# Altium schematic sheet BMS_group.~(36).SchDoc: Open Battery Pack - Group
size A3; Author: Morgane Vallée; Revision: 1.0; SheetNumber: 2; SheetTotal: 3
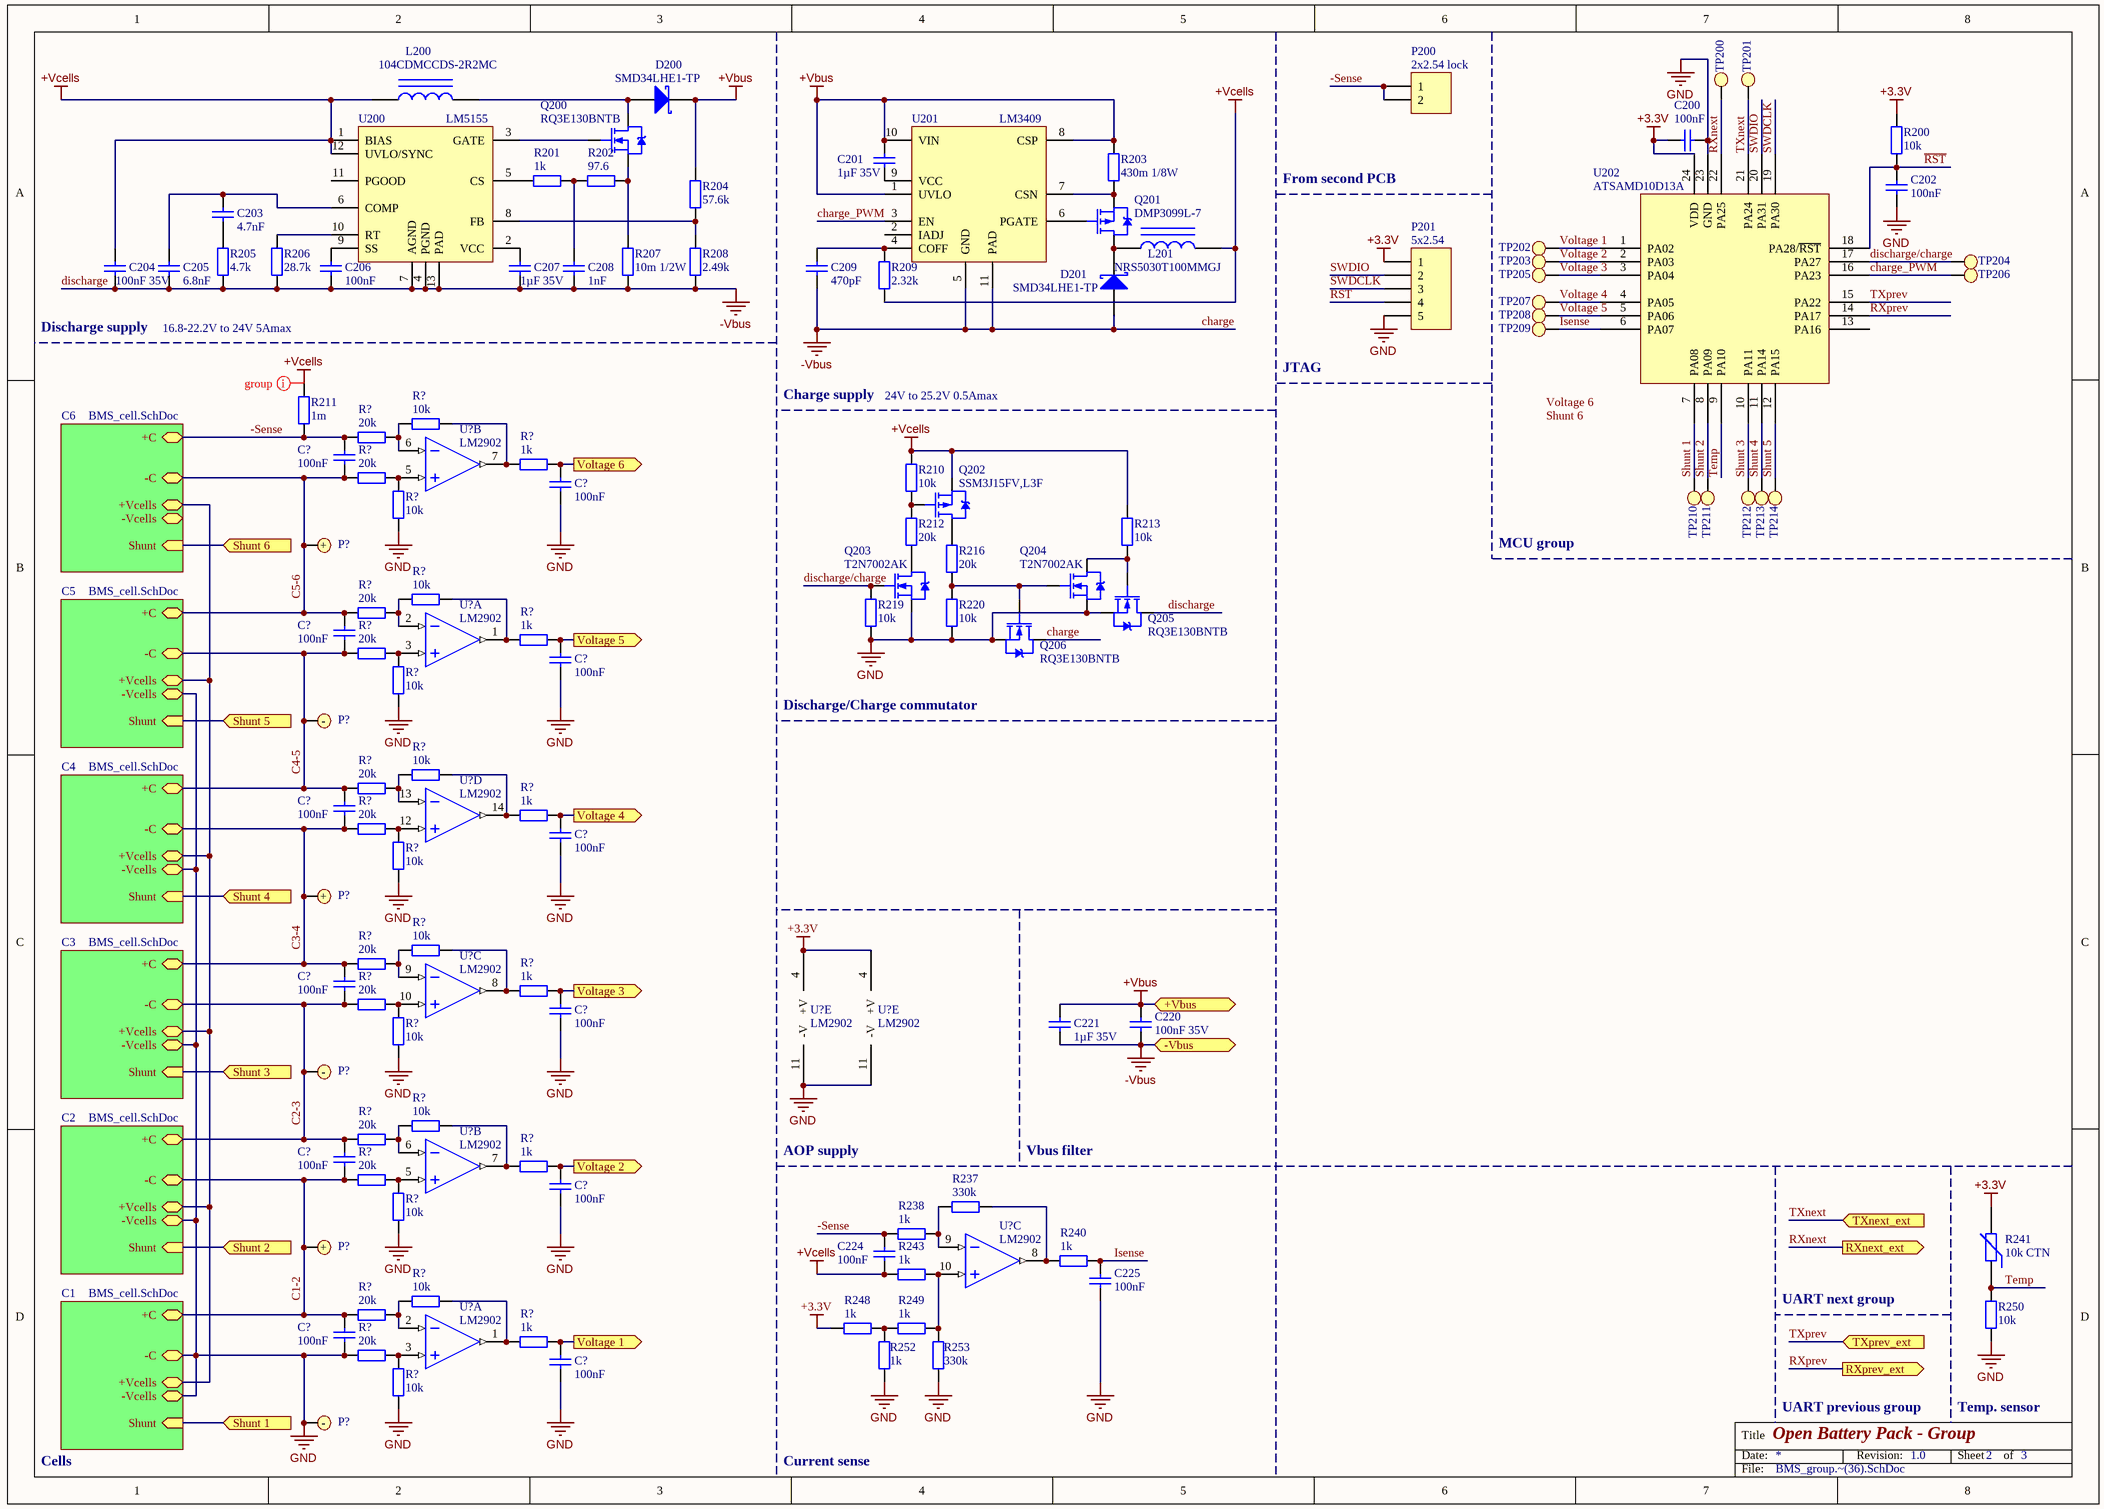
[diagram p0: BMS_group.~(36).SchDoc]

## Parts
(Parts that share a designator on the sheet are numbered #1, #2 ... from top to bottom, then left to right.)
C200  100nF  [C0603]
C201  1µF 35V  [C0805]
C202  100nF  [C0603]
C203  4.7nF  [C0603]
C204  100nF 35V  [C0603]
C205  6.8nF  [C0603]
C206  100nF  [C0603]
C207  1µF 35V  [C0805]
C208  1nF  [C0603]
C209  470pF  [C0603]
C220  100nF 35V  [C0603]
C221  1µF 35V  [C0805]
C224  100nF  [C0603]
C225  100nF  [C0603]
C?#1  100nF  [C0603]
C?#2  100nF  [C0603]
C?#3  100nF  [C0603]
C?#4  100nF  [C0603]
C?#5  100nF  [C0603]
C?#6  100nF  [C0603]
C?#7  100nF  [C0603]
C?#8  100nF  [C0603]
C?#9  100nF  [C0603]
C?#10  100nF  [C0603]
C?#11  100nF  [C0603]
C?#12  100nF  [C0603]
D200  SMD34LHE1-TP  [SOD-123H]
D201  SMD34LHE1-TP  [SOD-123H]
L200  104CDMCCDS-2R2MC  [SELF_SMD_8x8]
L201  NRS5030T100MMGJ  [SELF_SMD_4.9x4.9]
P200  2x2.54 lock  [MOLEX KK 0022272021]
P201  5x2.54  [HDR1X5]
P?#1  Bat+  [Keystone 241]  (value not drawn)
P?#2  Bat-  [Keystone 2993]  (value not drawn)
P?#3  Bat+  [Keystone 241]  (value not drawn)
P?#4  Bat-  [Keystone 2993]  (value not drawn)
P?#5  Bat+  [Keystone 241]  (value not drawn)
P?#6  Bat-  [Keystone 2993]  (value not drawn)
Q200  RQ3E130BNTB  [INFINEON PG-TSDSON-8]
Q201  DMP3099L-7  [DIODES SOT-23-3]
Q202  SSM3J15FV,L3F  [DIODES SOT-23-3]
Q203  T2N7002AK  [DIODES SOT-23-3]
Q204  T2N7002AK  [DIODES SOT-23-3]
Q205  RQ3E130BNTB  [INFINEON PG-TSDSON-8]
Q206  RQ3E130BNTB  [INFINEON PG-TSDSON-8]
R200  10k  [R0603]
R201  1k  [R0603]
R202  97.6  [R0603]
R203  430m 1/8W  [R0603]
R204  57.6k  [R0603]
R205  4.7k  [R0603]
R206  28.7k  [R0603]
R207  10m 1/2W  [R1206]
R208  2.49k  [R0603]
R209  2.32k  [R0603]
R210  10k  [R0603]
R211  1m  [R1206]
R212  20k  [R0603]
R213  10k  [R0603]
R216  20k  [R0603]
R219  10k  [R0603]
R220  10k  [R0603]
R237  330k  [R0603]
R238  1k  [R0603]
R240  1k  [R0603]
R241  10k CTN  [NTC 0402/1005]
R243  1k  [R0603]
R248  1k  [R0603]
R249  1k  [R0603]
R250  10k  [R0603]
R252  1k  [R0603]
R253  330k  [R0603]
R?#1  10k  [R0603]
R?#2  20k  [R0603]
R?#3  1k  [R0603]
R?#4  20k  [R0603]
R?#5  10k  [R0603]
R?#6  10k  [R0603]
R?#7  20k  [R0603]
R?#8  1k  [R0603]
R?#9  20k  [R0603]
R?#10  10k  [R0603]
R?#11  10k  [R0603]
R?#12  20k  [R0603]
R?#13  1k  [R0603]
R?#14  20k  [R0603]
R?#15  10k  [R0603]
R?#16  10k  [R0603]
R?#17  20k  [R0603]
R?#18  1k  [R0603]
R?#19  20k  [R0603]
R?#20  10k  [R0603]
R?#21  10k  [R0603]
R?#22  20k  [R0603]
R?#23  1k  [R0603]
R?#24  20k  [R0603]
R?#25  10k  [R0603]
R?#26  10k  [R0603]
R?#27  20k  [R0603]
R?#28  1k  [R0603]
R?#29  20k  [R0603]
R?#30  10k  [R0603]
TP200  Test Point  [Test Point]  (value not drawn)
TP201  Test Point  [Test Point]  (value not drawn)
TP202  Test Point  [Test Point]  (value not drawn)
TP203  Test Point  [Test Point]  (value not drawn)
TP204  Test Point  [Test Point]  (value not drawn)
TP205  Test Point  [Test Point]  (value not drawn)
TP206  Test Point  [Test Point]  (value not drawn)
TP207  Test Point  [Test Point]  (value not drawn)
TP208  Test Point  [Test Point]  (value not drawn)
TP209  Test Point  [Test Point]  (value not drawn)
TP210  Test Point  [Test Point]  (value not drawn)
TP211  Test Point  [Test Point]  (value not drawn)
TP212  Test Point  [Test Point]  (value not drawn)
TP213  Test Point  [Test Point]  (value not drawn)
TP214  Test Point  [Test Point]  (value not drawn)
U200  LM5155  [TI WSON-12]
U201  LM3409  [TI MSOP-10 DGQ]
U202  ATSAMD10D13A  [SMSC QFN-24 4x4MM]
U?#1  LM2902  [Atmel SO-14 14S1]  (part B of 5)
U?#2  LM2902  [Atmel SO-14 14S1]  (part A of 5)
U?#3  LM2902  [Atmel SO-14 14S1]  (part D of 5)
U?#4  LM2902  [Atmel SO-14 14S1]  (part C of 5)
U?#5  LM2902  [Atmel SO-14 14S1]  (part E of 5)
U?#6  LM2902  [Atmel SO-14 14S1]  (part E of 5)
U?#7  LM2902  [Atmel SO-14 14S1]  (part B of 5)
U?#8  LM2902  [Atmel SO-14 14S1]  (part C of 5)
U?#9  LM2902  [Atmel SO-14 14S1]  (part A of 5)

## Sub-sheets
C1 = BMS_cell.SchDoc: -C, +C, +Vcells, -Vcells, Shunt (in)
C2 = BMS_cell.SchDoc: -C, +C, +Vcells, -Vcells, Shunt (in)
C3 = BMS_cell.SchDoc: -C, +C, +Vcells, -Vcells, Shunt (in)
C4 = BMS_cell.SchDoc: -C, +C, +Vcells, -Vcells, Shunt (in)
C5 = BMS_cell.SchDoc: -C, +C, +Vcells, -Vcells, Shunt (in)
C6 = BMS_cell.SchDoc: -C, +C, +Vcells, -Vcells, Shunt (in)

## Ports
+Vbus, -Vbus, RXnext_ext (out), RXprev_ext (out), Shunt 1 (in), Shunt 2 (in), Shunt 3 (in), Shunt 4 (in), Shunt 5 (in), Shunt 6 (in), TXnext_ext (in), TXprev_ext (in), Voltage 1 (out), Voltage 2 (out), Voltage 3 (out), Voltage 4 (out), Voltage 5 (out), Voltage 6 (out)

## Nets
+3.3V: C200.2 P201.1 R200.2 R241.2 R248.2 U202.24(VDD) U?#5.4(+V) U?#6.4(+V)
+Vbus: C201.1 C220.1 C221.1 D200.3(K) R203.2 R204.2 U201.1(UVLO) U201.8(CSP) U201.10(VIN) ; port +Vbus
+Vcells: C204.1 C224.2 L200.1 L201.2 Q202.2(S) R209.2 R210.2 R211.2 R213.2 R243.2 U200.1(BIAS) U200.12(UVLO/SYNC)
charge: C204.2 C205.2 C206.2 C207.2 C208.2 C209.2 C220.2 C221.2 D201.1(A) Q205.3(D) Q206.3(D) R205.1 R206.1 R207.1 R208.1 U200.4(PGND) U200.7(AGND) U200.13(PAD) U201.5(GND) U201.11(PAD) ; port -Vbus  [also labelled -Vbus, discharge]
GND: C200.1 C202.1 C225.2 C?#2.2 C?#4.2 C?#6.2 C?#8.2 C?#10.2 C?#11.2 C?#12.2 P201.5 P?#6.1 Q203.2(S) Q204.2(S) Q205.2(S) Q206.2(S) R219.1 R220.1 R250.2 R252.2 R253.1 R?#5.2 R?#10.2 R?#15.2 R?#20.2 R?#25.2 R?#29.2 R?#30.2 U202.23(GND) U?#5.11(-V) U?#6.11(-V) ; sheet C1/-C, sheet C1/-Vcells, sheet C2/-Vcells, sheet C3/-Vcells, sheet C4/-Vcells, sheet C5/-Vcells
-Sense: C224.1 C?#1.1 P200.1 P200.2 R211.1 R238.1 R?#2.1 ; sheet C6/+C
C1-2: C?#9.2 C?#11.1 P?#5.1 R?#24.2 R?#27.1 ; sheet C1/+C, sheet C2/-C
C2-3: C?#7.2 C?#9.1 P?#4.1 R?#19.2 R?#22.1 ; sheet C2/+C, sheet C3/-C
C3-4: C?#5.2 C?#7.1 P?#3.1 R?#14.2 R?#17.1 ; sheet C3/+C, sheet C4/-C
C4-5: C?#3.2 C?#5.1 P?#2.1 R?#9.2 R?#12.1 ; sheet C4/+C, sheet C5/-C
C5-6: C?#1.2 C?#3.1 P?#1.1 R?#4.2 R?#7.1 ; sheet C5/+C, sheet C6/-C
charge_PWM: TP206.1 U201.3(EN) U202.16(PA23)
discharge/charge: Q203.1(G) R219.2 TP204.1 U202.17(PA27)
Isense: C225.1 R240.1 TP209.1 U202.6(PA07)
~{RST}: C202.2 P201.4 R200.1 U202.18(PA28/~{RST})
RXnext: TP200.1 U202.22(PA25) ; port RXnext_ext
RXprev: U202.14(PA17) ; port RXprev_ext
Shunt 1: TP210.1 U202.7(PA08)
Shunt 1: port Shunt 1, sheet C1/Shunt  [a separate net that carries the same name]
Shunt 2: TP211.1 U202.8(PA09)
Shunt 2: port Shunt 2, sheet C2/Shunt  [a separate net that carries the same name]
Shunt 3: TP212.1 U202.10(PA11)
Shunt 3: port Shunt 3, sheet C3/Shunt  [a separate net that carries the same name]
Shunt 4: TP213.1 U202.11(PA14)
Shunt 4: port Shunt 4, sheet C4/Shunt  [a separate net that carries the same name]
Shunt 5: TP214.1 U202.12(PA15)
Shunt 5: port Shunt 5, sheet C5/Shunt  [a separate net that carries the same name]
Shunt 6: port Shunt 6, sheet C6/Shunt
SWDCLK: P201.3 U202.19(PA30)
SWDIO: P201.2 U202.20(PA31)
Temp: R241.1 R250.1 U202.9(PA10)
TXnext: TP201.1 U202.21(PA24) ; port TXnext_ext
TXprev: U202.15(PA22) ; port TXprev_ext
Voltage 1: TP202.1 U202.1(PA02)
Voltage 1: C?#12.1 R?#28.1 ; port Voltage 1  [a separate net that carries the same name]
Voltage 2: TP203.1 U202.2(PA03)
Voltage 2: C?#10.1 R?#23.1 ; port Voltage 2  [a separate net that carries the same name]
Voltage 3: TP205.1 U202.3(PA04)
Voltage 3: C?#8.1 R?#18.1 ; port Voltage 3  [a separate net that carries the same name]
Voltage 4: TP207.1 U202.4(PA05)
Voltage 4: C?#6.1 R?#13.1 ; port Voltage 4  [a separate net that carries the same name]
Voltage 5: TP208.1 U202.5(PA06)
Voltage 5: C?#4.1 R?#8.1 ; port Voltage 5  [a separate net that carries the same name]
Voltage 6: C?#2.1 R?#3.1 ; port Voltage 6
NetC201_2: C201.2 U201.9(VCC)
NetC203_1: C203.1 C205.1 U200.6(COMP)
NetC203_2: C203.2 R205.2
NetC206_1: C206.1 U200.9(SS)
NetC207_1: C207.1 U200.2(VCC)
NetC208_1: C208.1 R201.1 R202.2
NetC209_1: C209.1 R209.1 U201.4(COFF)
NetD200_1: D200.1(A) L200.2 Q200.3(D)
NetD201_3: D201.3(K) L201.1 Q201.3(D)
NetQ200_1: Q200.1(G) U200.3(GATE)
NetQ200_2: Q200.2(S) R202.1 R207.2
NetQ201_1: Q201.1(G) U201.6(PGATE)
NetQ201_2: Q201.2(S) R203.1 U201.7(CSN)
NetQ202_1: Q202.1(G) R210.1 R212.2
NetQ202_3: Q202.3(D) R216.2
NetQ203_3: Q203.3(D) R212.1
NetQ204_1: Q204.1(G) Q206.1(G) R216.1 R220.2
NetQ204_3: Q204.3(D) Q205.1(G) R213.1
NetR201_2: R201.2 U200.5(CS)
NetR204_1: R204.1 R208.2 U200.8(FB)
NetR206_2: R206.2 U200.10(RT)
NetR237_1: R237.1 R240.2 U?#8.8(OUT)
NetR237_2: R237.2 R238.2 U?#8.9(IN-)
NetR243_1: R243.1 R249.1 R253.2 U?#8.10(IN+)
NetR248_1: R248.1 R249.2 R252.1
NetR?#1_1: R?#1.1 R?#2.2 U?#1.6(IN-)
NetR?#1_2: R?#1.2 R?#3.2 U?#1.7(OUT)
NetR?#4_1: R?#4.1 R?#5.1 U?#1.5(IN+)
NetR?#6_1: R?#6.1 R?#7.2 U?#2.2(IN-)
NetR?#6_2: R?#6.2 R?#8.2 U?#2.1(OUT)
NetR?#9_1: R?#9.1 R?#10.1 U?#2.3(IN+)
NetR?#11_1: R?#11.1 R?#12.2 U?#3.13(IN-)
NetR?#11_2: R?#11.2 R?#13.2 U?#3.14(OUT)
NetR?#14_1: R?#14.1 R?#15.1 U?#3.12(IN+)
NetR?#16_1: R?#16.1 R?#17.2 U?#4.9(IN-)
NetR?#16_2: R?#16.2 R?#18.2 U?#4.8(OUT)
NetR?#19_1: R?#19.1 R?#20.1 U?#4.10(IN+)
NetR?#21_1: R?#21.1 R?#22.2 U?#7.6(IN-)
NetR?#21_2: R?#21.2 R?#23.2 U?#7.7(OUT)
NetR?#24_1: R?#24.1 R?#25.1 U?#7.5(IN+)
NetR?#26_1: R?#26.1 R?#27.2 U?#9.2(IN-)
NetR?#26_2: R?#26.2 R?#28.2 U?#9.1(OUT)
NetR?#29_1: R?#29.1 R?#30.1 U?#9.3(IN+)
(unnamed): sheet C1/+Vcells, sheet C2/+Vcells, sheet C3/+Vcells, sheet C4/+Vcells, sheet C5/+Vcells, sheet C6/+Vcells

Not connected (* = marked no-connect by the designer): U200 11(PGOOD); U201 2(IADJ); U202 13(PA16)

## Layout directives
net class Group: +Vcells

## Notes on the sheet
- From second PCB
- Discharge supply
- 16.8-22.2V to 24V 5Amax
- JTAG
- Charge supply
- 24V to 25.2V 0.5Amax
- MCU group
- Discharge/Charge commutator
- AOP supply
- Vbus filter
- UART next group
- UART previous group
- Temp. sensor
- Cells
- Current sense
- Labels drawn without touching a wire or pin: Shunt 6, Voltage 6

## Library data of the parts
C200-C209 C220 C221 C224 C225 C?#1-C?#12 = Cap: Capacitor
D200 D201 = Diode BAT17
L200 L201 = Inductor Iron: Magnetic-Core Inductor
P200 = Header 2: Header, 2-Pin
P201 = Header 5: Header, 5-Pin
P?#1 P?#3 P?#5 = Bat+: Battery contact +
P?#2 P?#4 P?#6 = Bat-: Battery contact -
Q200 Q203-Q206 = MOSFET_N
Q201 Q202 = MOSFET_P
R200-R213 R216 R219 R220 R237 R238 R240 R243 R248-R250 R252 R253 R?#1-R?#30 = Res2: Resistor
R241 = Res Varistor: Varistor (Voltage-Sensitive Resistor)
U200 = LM5155: 2.2-MHz Wide Input Nonsynchronous Boost, SEPIC, Flyback Controller
U201 = LM3409: P-FET Buck Controller for High-Power LED Drivers
U?#1-U?#9 = LM2902: Low-power quad operational amplifiers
